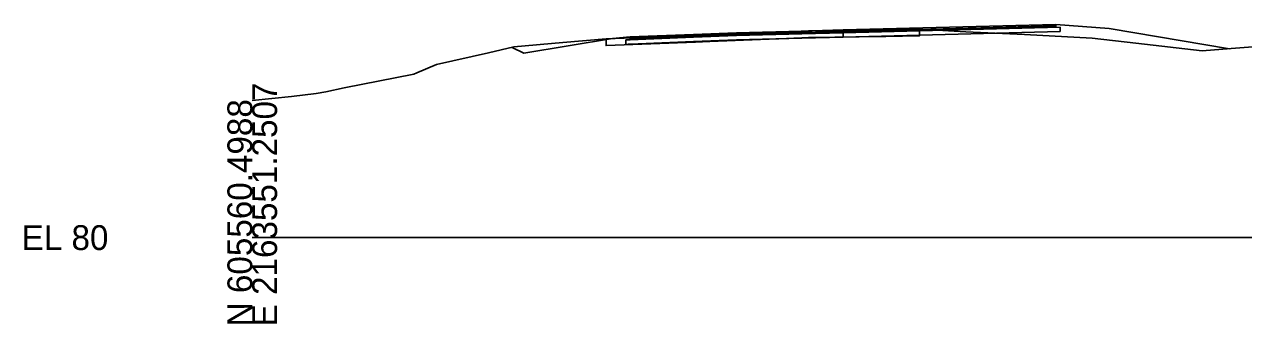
# Model space of a CAD drawing. Extents: x -26 to 1303, y -10 to 12033.
# Drawn here: x -25.7 to 111.8, y 5990.3 to 6024 of the extents above; entities that cross this region are included whole.
import ezdxf

# ---------------------------------------------------------------- set-up
doc = ezdxf.new("R2010")
doc.units = 0
for name, color, linetype in [('RD_GPK_XS_Cell', 7, 'Continuous'), ('RD_XS_Base', 7, 'Continuous'), ('RD_XS_ExGround', 7, 'Continuous'), ('RD_XS_ExPaveRet', 7, 'Continuous'), ('RD_XS_Greenside', 7, 'Continuous'), ('RD_XS_Pave', 7, 'Continuous'), ('RD_XS_PaveOvlay_CP', 7, 'Continuous'), ('RD_XS_TieSlope', 7, 'Continuous')]:
    doc.layers.add(name, color=color, linetype=linetype)

msp = doc.modelspace()

# ---------------------------------------------------------------- linework, layer by layer
at = {"layer": 'RD_GPK_XS_Cell'}
msp.add_line((0, 6000), (150, 6000), dxfattribs=at)
at = {"layer": 'RD_XS_Base'}
for p, q in [((66.62, 6023.09), (91.12, 6023.73)), ((90.62, 6023.72), (90.62, 6023.72)), ((90.62, 6023.72), (90.62, 6023.72)), ((90.62, 6023.72), (90.62, 6023.72)), ((91.12, 6023.73), (91.12, 6023.23)), ((91.12, 6023.7), (91.12, 6023.7)), ((42.41, 6022.29), (42.12, 6022.28)), ((42.12, 6022.28), (42.12, 6022.07)), ((42.12, 6022.07), (42.12, 6021.78)), ((42.62, 6022.3), (42.41, 6022.29)), ((49.75, 6022.59), (42.62, 6022.3)), ((42.62, 6021.8), (49.75, 6022.09)), ((54.62, 6022.78), (49.75, 6022.59)), ((49.75, 6022.09), (54.62, 6022.28)), ((61.96, 6022.97), (54.62, 6022.78)), ((54.62, 6022.28), (61.96, 6022.47)), ((66.62, 6023.09), (61.96, 6022.97)), ((61.96, 6022.47), (66.62, 6022.59)), ((66.62, 6022.59), (66.62, 6023.25)), ((66.62, 6023.25), (66.62, 6023.25)), ((66.62, 6023.25), (66.62, 6023.25)), ((66.62, 6023.25), (66.62, 6023.09)), ((91.12, 6023.23), (66.62, 6022.59)), ((66.62, 6023.09), (66.62, 6023.09)), ((66.62, 6022.59), (66.62, 6023.09)), ((66.62, 6023.09), (66.62, 6023.09)), ((66.62, 6023.09), (66.62, 6023.09)), ((66.62, 6022.59), (66.62, 6022.59)), ((90.62, 6023.22), (90.62, 6023.22)), ((90.62, 6023.22), (90.62, 6023.22)), ((42.12, 6021.78), (42.41, 6021.79)), ((42.41, 6021.79), (42.62, 6021.8))]:
    msp.add_line(p, q, dxfattribs=at)
at = {"layer": 'RD_XS_ExGround'}
msp.add_lwpolyline([(0, 6015.44), (4.41, 6015.91), (7.21, 6016.25), (8.29, 6016.44), (10.35, 6016.88), (18.22, 6018.43), (18.56, 6018.56), (20.78, 6019.5), (26.65, 6020.84), (29.51, 6021.5), (35.03, 6022), (39.91, 6022.4), (51.92, 6022.87), (59.35, 6023.16), (61.02, 6023.23), (62.74, 6023.3), (71.18, 6023.43), (75.26, 6023.51), (80.46, 6023.2), (87.07, 6022.88), (94.71, 6022.5), (99.64, 6021.92), (107.12, 6021.07), (110.39, 6021.31), (121.05, 6022.13)], dxfattribs=at)
at = {"layer": 'RD_XS_ExPaveRet'}
for points in [[(75.26, 6023.51), (75.26, 6023.49), (75.26, 6022.76), (75.26, 6022.76), (71.44, 6022.68), (71.18, 6022.68), (62.95, 6022.55), (62.74, 6022.55), (61.24, 6022.49), (61.09, 6022.48), (59.39, 6022.42), (59.36, 6022.41), (59.35, 6022.41), (59.24, 6022.41), (51.59, 6022.11), (50, 6022.05), (39.91, 6021.65), (39.91, 6021.65), (39.91, 6021.65), (39.91, 6022.31), (39.91, 6022.4), (39.91, 6022.4), (39.91, 6022.4), (50, 6022.8), (51.59, 6022.86), (59.24, 6023.16), (59.35, 6023.16), (59.36, 6023.16), (59.39, 6023.17), (61.09, 6023.23), (61.24, 6023.24), (62.74, 6023.3), (62.95, 6023.3), (71.18, 6023.43), (71.44, 6023.43), (75.26, 6023.51), (75.26, 6023.51)], [(71.44, 6023.43), (71.18, 6023.43), (62.95, 6023.3), (62.74, 6023.3), (61.24, 6023.24), (61.09, 6023.23), (59.39, 6023.17), (59.36, 6023.16), (59.35, 6023.16), (59.24, 6023.16), (51.59, 6022.86), (50, 6022.8), (39.91, 6022.4), (39.91, 6022.4), (39.91, 6022.31), (39.91, 6021.65), (39.91, 6021.65), (50, 6022.05), (51.59, 6022.11), (59.24, 6022.41), (59.35, 6022.41), (59.36, 6022.41), (59.39, 6022.42), (61.09, 6022.48), (61.24, 6022.49), (62.74, 6022.55), (62.95, 6022.55), (71.18, 6022.68), (71.44, 6022.68), (75.26, 6022.76), (75.26, 6023.49), (75.26, 6023.51), (71.44, 6023.43)]]:
    msp.add_lwpolyline(points, dxfattribs=at)
at = {"layer": 'RD_XS_Greenside'}
for p, q in [((96.62, 6023.56), (110.2, 6021.29)), ((40.62, 6022.46), (30.62, 6020.79)), ((30.62, 6020.79), (29.3, 6021.45))]:
    msp.add_line(p, q, dxfattribs=at)
at = {"layer": 'RD_XS_Pave'}
for p, q in [((66.62, 6023.41), (61.96, 6023.29)), ((90.62, 6024.04), (66.62, 6023.41)), ((90.62, 6023.88), (66.62, 6023.25)), ((66.62, 6023.25), (90.62, 6023.88)), ((66.62, 6023.09), (90.62, 6023.72)), ((66.62, 6023.41), (66.62, 6023.41)), ((90.62, 6023.88), (90.62, 6024.04)), ((90.62, 6024.04), (90.62, 6024.04)), ((90.62, 6024.04), (90.62, 6024.04)), ((90.62, 6024.04), (90.62, 6024.04)), ((90.62, 6023.72), (90.62, 6023.88)), ((90.62, 6023.88), (90.62, 6023.88)), ((90.62, 6023.88), (90.62, 6023.88)), ((90.62, 6023.88), (90.62, 6023.88)), ((90.62, 6023.88), (90.62, 6023.88)), ((90.62, 6023.88), (90.62, 6023.88)), ((90.62, 6023.72), (90.62, 6023.72)), ((90.62, 6023.72), (90.62, 6023.72)), ((49.75, 6022.91), (42.62, 6022.62)), ((42.62, 6022.46), (49.75, 6022.75)), ((49.75, 6022.75), (42.62, 6022.46)), ((42.62, 6022.62), (42.62, 6022.56)), ((42.62, 6022.3), (49.75, 6022.59)), ((42.62, 6022.56), (42.62, 6022.46)), ((42.62, 6022.46), (42.62, 6022.4)), ((42.62, 6022.4), (42.62, 6022.3)), ((54.62, 6023.1), (49.75, 6022.91)), ((49.75, 6022.75), (54.62, 6022.94)), ((54.62, 6022.94), (49.75, 6022.75)), ((49.75, 6022.59), (54.62, 6022.78)), ((61.96, 6023.29), (54.62, 6023.1)), ((54.62, 6022.94), (61.96, 6023.13)), ((61.96, 6023.13), (54.62, 6022.94)), ((54.62, 6022.78), (61.96, 6022.97)), ((61.96, 6023.13), (66.62, 6023.25)), ((66.62, 6023.25), (61.96, 6023.13)), ((61.96, 6022.97), (66.62, 6023.09)), ((66.62, 6023.25), (66.62, 6023.25)), ((66.62, 6023.25), (66.62, 6023.25)), ((66.62, 6023.25), (66.62, 6023.09)), ((66.62, 6023.25), (66.62, 6023.25)), ((66.62, 6023.09), (66.62, 6023.25)), ((66.62, 6023.25), (66.62, 6023.25)), ((66.62, 6023.25), (66.62, 6023.25)), ((66.62, 6023.09), (66.62, 6023.09)), ((66.62, 6023.09), (66.62, 6023.09))]:
    msp.add_line(p, q, dxfattribs=at)
at = {"layer": 'RD_XS_PaveOvlay_CP'}
for p, q in [((66.62, 6023.41), (61.96, 6023.29)), ((90.62, 6024.04), (66.62, 6023.41)), ((66.62, 6023.41), (66.62, 6023.41)), ((90.62, 6024.04), (90.62, 6024.04)), ((90.62, 6024.04), (90.62, 6024.04)), ((49.75, 6022.91), (42.62, 6022.62)), ((54.62, 6023.1), (49.75, 6022.91)), ((61.96, 6023.29), (54.62, 6023.1))]:
    msp.add_line(p, q, dxfattribs=at)
at = {"layer": 'RD_XS_TieSlope'}
for p, q in [((90.62, 6024.04), (96.62, 6023.56)), ((42.62, 6022.62), (40.62, 6022.46))]:
    msp.add_line(p, q, dxfattribs=at)

# ---------------------------------------------------------------- texts
at = {"layer": 'RD_GPK_XS_Cell'}
for s, p in [('E 2163551.2507', (2.8, 5990)), ('N 605560.4988', (0, 5990))]:
    msp.add_text(s, height=2.8, rotation=90, dxfattribs=at).set_placement(p)
msp.add_text('EL 80', height=2.8, dxfattribs=at).set_placement((-26, 5998.6))

doc.saveas('drawing.dxf')
